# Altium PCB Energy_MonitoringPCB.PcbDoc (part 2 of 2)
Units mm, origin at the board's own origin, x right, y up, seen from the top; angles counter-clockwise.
Board outline 101.22 x 43.37 mm, 4 copper layers (Top Layer, Int1 (GND), Int2 (PWR), Bottom Layer), stack 1.527 mm thick; 86 components, 79 nets, 384 pads, 136 vias.
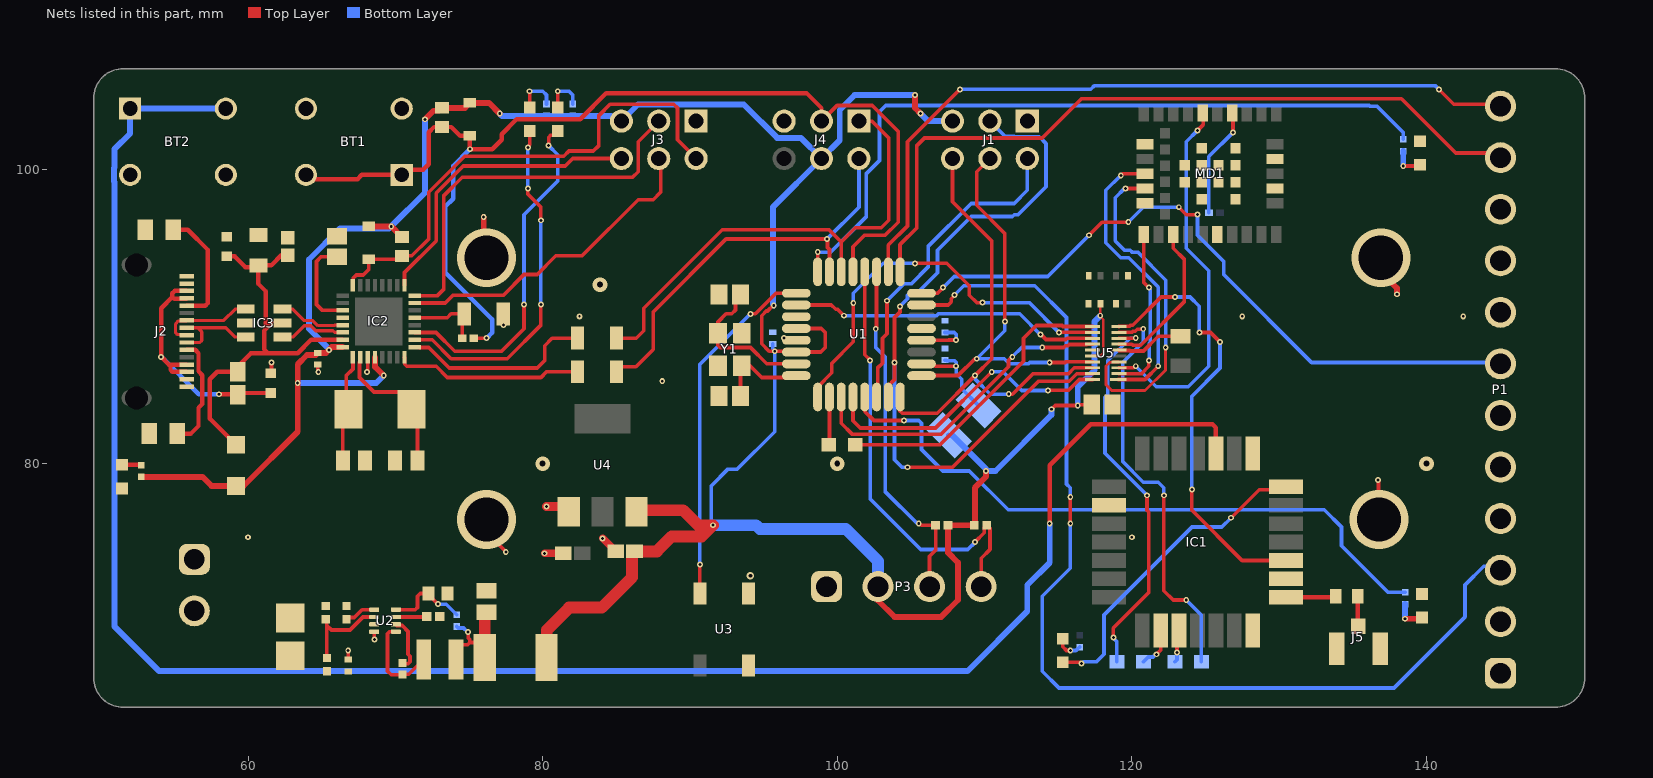
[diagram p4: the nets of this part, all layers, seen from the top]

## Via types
v1: diameter 0.4, hole 0.2, Top Layer to Bottom Layer, 120 vias
v2: diameter 0.4, hole 0.16, Top Layer to Bottom Layer, 6 vias
v3: diameter 1, hole 0.4, Top Layer to Bottom Layer, 4 vias
v4: diameter 4, hole 3, Top Layer to Bottom Layer, 4 vias
v5: diameter 0.4, hole 0.2, Top Layer to Int2 (PWR), 1 vias
v6: diameter 0.508, hole 0.254, Top Layer to Int1 (GND), 1 vias

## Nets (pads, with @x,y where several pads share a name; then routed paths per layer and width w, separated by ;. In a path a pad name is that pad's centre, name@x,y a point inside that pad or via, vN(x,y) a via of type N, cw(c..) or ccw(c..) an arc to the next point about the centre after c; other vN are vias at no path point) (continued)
+5V_OUT: C6.2 C15.2 C24.2 C25.2 C26.2 D1.1 D4.1 D5.1 F1.2 IC2.4 IC2.32 J1.5 J3.5 J4.4 L2.2 P3.2 R7.1 R10.1 R13.1 R14.1 R16.1 R17.1 R25.1 U1.4 U1.6 U4.3 U5.16 | length 210.8
  Top Layer w0.17: U5.16@117.326,87.31 117.341,87.325 117.873,87.325 118.061,87.512 118.061,89.776 117.856,89.981 117.856,90.856 C24.2@117.864,90.864
  Top Layer w0.25: v1(95.691,90.745) 95.651,90.745 95.269,90.362 95.188,90.362 94.869,90.043 94.869,88.138 95.377,87.63 v1(95.758,87.63) 96.774,87.63 96.831,87.573 U1.6@97.223,87.573 98.876,87.573 99.187,87.884 99.187,88.9 98.914,89.173 U1.4@97.223,89.173 ; v1(114.554,83.693) 114.808,83.947 v1(116.332,83.947) 116.39,84.005 C25.2@117.283,84.005
  Top Layer w0.4: R7.1@52.739,79.102 56.915,79.102 57.531,78.486 59.179,78.486 D5.1@59.182,78.483 59.687,78.483 63.373,82.169 v1(63.373,85.471) 63.373,86.741 64.008,87.376 64.596,87.376 C26.2@64.742,87.522 65.297,87.522 v1(65.49,87.715) 65.683,87.908 IC2.32@66.421,87.908 ; D4.1@68.199,96.111 v1(69.724,96.111) R25.1@70.443,95.392 ; IC2.4@68.621,87.208 68.621,86.573 v1(69.215,85.979) ; v1(72.009,103.378) 72.586,103.955 72.952,103.955 R10.1@73.152,104.155 74.719,104.155 D1.1@75.057,104.493 76.355,104.493 v1(77.089,103.759) ; P3.2@102.771,71.653 102.771,70.711 103.886,69.596 107.061,69.596 108.204,70.739 108.204,73.279 107.53,73.953 R16.1@107.53,75.819 R17.1@109.303,75.819 109.347,75.819 109.347,78.359 110.109,79.121 v1(110.109,79.502) ; v1(105.283,105.029) 105.283,104.14 v1(105.664,103.759)
  Top Layer w0.8: F1.2@80.273,66.836 80.273,68.698 81.8,70.225 84.01,70.225 86.073,72.288 86.073,73.875 C6.2@86.239,74.041 87.757,74.041 88.773,75.057 90.805,75.057 v1(91.567,75.819) 90.551,75.819 89.535,76.835 86.476,76.835 U4.3@86.374,76.733
  Bottom Layer w0.25: v1(91.567,75.819) 91.44,75.946 91.44,78.486 92.583,79.629 93.218,79.629 95.758,82.169 v1(95.758,87.63) 95.631,87.757 C15.2@95.631,88.119
  Bottom Layer w0.4: v1(63.373,85.471) 68.707,85.471 v1(69.215,85.979) ; v1(65.49,87.715) 65.49,87.799 64.135,89.154 64.135,93.853 66.252,95.97 69.583,95.97 v1(69.724,96.111) 72.009,98.396 v1(72.009,103.378) ; v1(77.089,103.759) 77.235,103.613 R13.1@80.264,103.613 R14.1@82.042,103.613 84.665,103.613 85.027,103.251 J3.5@85.344,103.251 86.479,104.386 93.653,104.386 95.923,102.116 97.528,102.116 J4.4@98.933,100.711 ; v1(95.691,90.745) 95.631,90.805 95.631,97.409 J4.4@98.933,100.711 ; v1(105.283,105.029) 101.186,105.029 100.171,104.014 100.171,101.949 J4.4@98.933,100.711 ; v1(105.664,103.759) 106.172,103.251 J1.5@107.826,103.251 ; L2.2@107.577,81.93 107.808,81.93 110.109,79.629 v1(110.109,79.502) 110.744,79.502 114.554,83.312 v1(114.554,83.693) ; v1(116.332,83.947) 116.332,85.217 117.475,86.36 117.475,89.662 v1(117.856,90.043)
  Bottom Layer w0.8: v1(91.567,75.819) 94.488,75.819 94.742,75.565 100.584,75.565 102.771,73.378 P3.2@102.771,71.653
+12V_IN: C2.1 C3.2 P1.1 P1.5 P1.9 P2.2 R1.2 U2.3
CC1: J2.A5 R8.2 | length 8
  Top Layer w0.3: R8.2@54.925,95.885 55.9,95.885 57.277,94.508 57.277,90.901 57.101,90.725 J2.A5@55.839,90.725
CC2: J2.B5 R9.2 | length 7.7
  Top Layer w0.3: R9.2@55.179,82.042 56.124,82.042 56.639,82.556 56.639,83.792 56.896,84.049 56.896,86.006 56.639,86.264 56.639,86.572 56.639,87.499 56.413,87.725 J2.B5@55.839,87.725
DTR_RESET: BT1.1 BT1.2 C20.2 D1.2 J4.3 R10.2 U1.29 | length 76
  Top Layer w0.25: C20.2@75.32,88.516 75.323,88.519 v1(76.2,88.519) ; J4.3@98.933,103.251 99.993,104.311 102.372,104.311 104.14,102.543 104.14,96.393 103.251,95.504 101.854,95.504 101.073,94.723 U1.29@101.073,93.023
  Top Layer w0.3: BT1.2@63.933,99.604 64.223,99.314 67.437,99.314 67.727,99.604 BT1.1@70.433,99.604 70.778,99.949 71.882,99.949 72.263,100.33 72.263,102.489 72.629,102.855 R10.2@73.152,102.855 73.802,102.855 74.394,102.263 D1.2@75.057,102.263 v1(75.057,101.346) 76.581,101.346 77.216,101.981 77.216,102.362 78.232,103.378 82.55,103.378 84.328,105.156 97.917,105.156 98.933,104.14 J4.3@98.933,103.251
  Bottom Layer w0.3: v1(75.057,101.346) 73.925,100.214 73.925,97.986 73.406,97.467 73.406,92.964 76.581,89.789 76.581,88.9 v1(76.2,88.519)
GND: BT1.3 BT1.4 BT2.3 BT2.4 C2.2 C3.1 C4.1 C5.2 C6.1 C7.1 C8.2 C9.2 C10.2 C11.2 C12.1 C13.1 C14.1 C15.1 C16.1 C17.2 C18.2 C19.2 C21.1 C22.1 C23.1 C24.1 C25.1 C26.1 IC1.2 IC1.14 IC1.16 IC1.22 IC2.3 IC2.28 IC3.2 J1.1 J2.A1 J2.A12 J2.B1 J2.B12 J3.1 J4.5 J5.2 J5.3 LED1.1 LED2.1 LED3.1 MD1.6 MD1.12 MD1.14 MD1.26 MD1.30 MD1.37 MD1.38 MD1.39 MD1.40 MD1.41 MD1.42 MD1.43 MD1.44 MD1.45 MD1.46 MD1.47 MD1.48 P1.2 P1.4 P1.6 P1.8 P1.10 P2.1 P3.1 R3.1 R4.1 R5.1 R8.1 R9.1 R15.2 U1.3 U1.5 U1.21 U2.4 U3.2 U3.3 U4.1 U5.15 Y1.2 Y1.4 | length 18.8
  Top Layer w0.25: C8.2@61.542,86.146 61.595,86.199 v1(61.595,86.868) ; C26.1@64.742,86.722 64.742,86.261 v1(64.77,86.233) ; C3.1@66.802,66.694 v1(66.802,67.31) ; v1(68.072,86.233) 68.121,86.282 IC2.3@68.121,87.208 ; U2.4@68.564,68.588 68.564,68.088 v1(68.58,68.072) ; U4.1@81.418,77.089 U4.1@81.774,76.733 ; v1@84.074,74.924 v1(84.074,74.93)
  Top Layer w0.254: v4(76.2,76.2) 76.2,75.34 77.5,74.04 v1(77.5,74) ; v1(136.725,78.9) 136.752,78.873 136.752,76.227 v4(136.779,76.2)
  Top Layer w0.4: v1(76,96.75) 76,94.18 v4(76.2,93.98) ; v4(136.906,93.98) 136.906,93.006 138,91.912 v1(138,91.5)
  Top Layer w0.5: v1(80.137,73.914) C7.1@81.401,73.914 ; v1@84.074,74.924 C6.1@84.957,74.041
  Top Layer w0.6: v1(80.264,77.089) U4.1@81.418,77.089
  other v1: 96.393,88.519 77.343,89.408
  other v2: 60,75 120,75 88.125,85.6 82.5,90 127.5,90 142.5,90
  other v3: 80,80 100,80 140,80 83.9,92.15
  other v6: 94.107,72.39
ICSP_CLK: J1.4 U1.17 U5.17 | length 27.8
  Top Layer w0.25: U1.17@105.723,85.973 106.42,85.973 106.426,85.979 108.204,85.979 109.347,87.122 v1(109.474,87.122) ; J1.4@110.366,100.711 109.474,99.819 109.474,97.536 111.379,95.631 v1(111.379,89.662) ; v1(114.427,86.868) 115.484,86.868 115.525,86.91 U5.17@117.326,86.91
  Bottom Layer w0.25: v1(111.379,89.662) 111.379,89.027 v1(109.474,87.122) 111.342,87.122 111.69,86.774 112.991,86.774 113.085,86.868 v1(114.427,86.868)
ICSP_MISO: J1.6 U1.16 U5.18 | length 33.2
  Top Layer w0.25: U1.16@104.273,84.523 104.273,84.703 104.267,84.709 104.267,83.566 104.41,83.423 106.791,83.423 v1(109.347,85.979) 110.49,87.122 110.49,95.123 107.826,97.787 J1.6@107.826,100.711 ; v1(111.646,84.714) 111.892,84.714 113.284,86.106 115.697,86.106 116.101,86.51 U5.18@117.326,86.51
  Bottom Layer w0.25: v1(109.347,85.979) 109.347,85.752 110.385,84.714 v1(111.646,84.714)
ICSP_MOSI: J1.3 U1.15 U5.19 | length 51
  Top Layer w0.25: U1.15@103.473,84.523 103.473,85.293 103.886,85.706 v1(103.886,86.868) 103.886,89.916 104.267,90.297 v1(104.267,90.678) ; v1(104.775,79.756) 107.823,79.756 113.665,85.598 115.755,85.598 116.266,86.11 U5.19@117.326,86.11
  Bottom Layer w0.25: v1(103.886,86.868) 103.886,80.264 104.394,79.756 v1(104.775,79.756) ; v1(104.267,90.678) 104.775,91.186 104.775,91.44 104.902,91.567 105.41,91.567 106.807,92.964 106.807,94.488 109.093,96.774 111.887,96.774 112.014,96.901 112.268,96.901 114.173,98.806 114.173,101.727 113.709,102.191 112.007,102.191 111.963,102.235 111.382,102.235 J1.3@110.366,103.251
ICSP_SS: J1.2 U1.14 | length 22.4
  Top Layer w0.25: U1.14@102.673,84.523 102.673,85.147 102.743,85.217 102.743,86.487 103.073,86.817 103.073,88.511 103.378,88.816 v1(103.378,91.059)
  Bottom Layer w0.25: v1(103.378,91.059) 104.535,92.216 105.043,92.216 106.172,93.345 106.172,94.742 109.093,97.663 112.014,97.663 112.906,98.555 J1.2@112.906,100.711
L_LIVE: D3.1 IC1.21 | length 21.7
  Top Layer w0.25: D3.1@115.316,66.51 116.497,66.51 v1(116.586,66.421) ; v1(126.746,76.327) 128.651,78.232 130.266,78.232 IC1.21@130.46,78.426
  Bottom Layer w0.25: v1(116.586,66.421) 116.713,66.548 117.602,66.548 118.11,67.056 118.11,69.723 124.079,75.692 126.111,75.692 v1(126.746,76.327)
LL_NRST: IC1.17 U5.10 | length 30
  Top Layer w0.25: U5.10@119.126,89.31 119.151,89.335 119.847,89.335 119.907,89.394 120.07,89.394 121.989,91.313 v1(122.936,91.313) ; v1(124.079,78.232) 124.079,76.835 127.488,73.426 IC1.17@130.46,73.426 ; v1(124.587,88.9) 125.349,88.9 v1(125.984,88.265)
  Bottom Layer w0.25: v1(122.936,91.313) 123.952,91.313 124.587,90.678 v1(124.587,88.9) ; v1(124.079,78.232) 124.079,84.582 125.984,86.487 v1(125.984,88.265)
LLRX: R21.1 U5.9 | length 28.3
  Top Layer w0.25: U5.9@119.126,88.91 119.988,88.91 120.072,88.994 120.236,88.994 120.367,89.125 120.748,89.125 v1(120.777,89.154) ; v1(122.174,77.851) 122.174,71.374 122.809,70.739 v1(123.698,70.739)
  Bottom Layer w0.25: v1(120.777,89.154) 120.777,88.265 119.38,86.868 119.38,80.137 120.777,78.74 121.793,78.74 122.174,78.359 v1(122.174,77.851) ; v1(123.698,70.739) 124.725,69.712 R21.1@124.725,66.548
LLTX: R20.1 U5.8 | length 26.5
  Top Layer w0.25: v1(118.745,68.199) 118.745,68.834 121.158,71.247 121.158,76.708 121.031,76.835 v1(121.031,77.851) ; U5.8@119.126,88.51 120.26,88.51 v1(120.269,88.519)
  Bottom Layer w0.25: v1(118.745,68.199) 118.745,68.158 118.988,67.915 R20.1@118.988,66.548 ; v1(120.269,88.519) 119.888,88.519 118.364,86.995 118.364,84.686 118.176,84.498 118.176,80.706 v1(121.031,77.851)
LNRST: R22.1 U1.10 | length 3.2
  Top Layer w0.25: R22.1@99.473,81.28 U1.10@99.473,84.523
LoRa_live: D3.2 R24.1 | length 1.9
  Top Layer w0.25: D3.2@115.316,68.11 115.316,67.564 115.57,67.31 v1(115.824,67.31)
  Bottom Layer w0.25: v1(115.824,67.31) 116.205,67.31 116.459,67.564 R24.1@116.459,67.545
LoRa_RST: BT2.1 BT2.2 IC1.24 | length 131.9
  Top Layer w0.3: v1(114.427,75.946) 114.427,79.883 117.221,82.677 125.476,82.677 125.71,82.443 IC1.24@125.71,80.676
  Bottom Layer w0.4: BT2.2@58.495,104.104 BT2.1@51.995,104.104 51.995,102.414 50.927,101.346 50.927,100.092 50.895,100.06 50.895,99.148 50.927,99.116 50.927,68.961 53.975,65.913 108.839,65.913 112.903,69.977 112.903,71.755 114.427,73.279 v1(114.427,75.946)
LORARX: IC1.10 R21.2 | length 2.2
  Top Layer w0.25: v1(123.063,67.183) 123.063,68.159 123.21,68.306 IC1.10@123.21,68.676
  Bottom Layer w0.25: R21.2@122.925,66.548 123.063,66.686 v1(123.063,67.183)
LORATX: IC1.9 R20.2 | length 2.8
  Top Layer w0.25: v1(121.666,67.056) 121.96,67.35 IC1.9@121.96,68.676
  Bottom Layer w0.25: R20.2@120.788,66.548 121.113,66.873 121.442,66.873 121.625,67.056 v1(121.666,67.056)
MCU_AVCC: C14.2 L2.1 U1.18 | length 6.8
  Top Layer w0.25: U1.18@105.723,86.773 106.493,86.773 106.652,86.614 v1(108.077,86.614)
  Bottom Layer w0.25: C14.2@107.315,87.027 107.41,87.027 107.442,86.995 107.95,86.995 108.077,86.868 v1(108.077,86.614) 108.077,86.106 108.458,85.725 108.458,85.082 L2.1@109.593,83.947
MNRST: R22.2 U5.11 | length 20.5
  Top Layer w0.25: R22.2@101.144,81.28 106.98,81.28 112.649,86.949 112.649,88.519 113.505,89.375 115.259,89.375 115.324,89.31 U5.11@117.326,89.31
MRX: U1.9 U5.12 | length 27.4
  Top Layer w0.25: U1.9@98.673,84.523 98.673,85.211 99.625,86.163 99.625,86.8 101.092,88.267 v1(101.092,90.901) ; v1(105.283,93.599) 107.442,93.599 108.966,92.075 108.966,91.44 109.474,90.932 v1(109.855,90.932) ; v1(115.062,88.9) 115.072,88.91 U5.12@117.326,88.91
  Bottom Layer w0.25: v1(101.092,90.901) 101.092,91.567 103.124,93.599 v1(105.283,93.599) ; v1(109.855,90.932) 113.03,90.932 v1(115.062,88.9)
MTX: U1.2 U5.13 | length 21.2
  Top Layer w0.25: U1.2@97.223,90.773 99.6,90.773 99.899,90.474 100.026,90.474 v1(100.457,90.043) ; v1(113.792,88.773) 113.833,88.773 114.181,88.425 115.524,88.425 115.608,88.51 U5.13@117.326,88.51
  Bottom Layer w0.25: v1(100.457,90.043) 106.739,90.043 106.87,90.175 112.39,90.175 v1(113.792,88.773)
OSC1: C12.2 U1.7 Y1.1 | length 10.1
  Top Layer w0.25: C12.2@93.435,91.486 93.091,91.142 93.091,90.424 92.837,90.17 92.456,90.17 91.91,89.624 Y1.1@91.91,88.857 91.91,88.049 92.077,87.882 94.109,87.882 95.218,86.773 U1.7@97.223,86.773
OSC2: C13.2 U1.8 Y1.3 | length 6.2
  Top Layer w0.25: C13.2@93.435,84.582 93.435,86.582 Y1.3@93.51,86.657 94.064,86.657 94.869,85.852 97.102,85.852 U1.8@97.223,85.973
PROG_RX: J4.2 R12.1 U1.31 | length 28.2
  Top Layer w0.25: R12.1@85.018,86.233 85.018,86.261 85.343,86.586 86.332,86.586 87.503,87.757 87.503,90.297 92.456,95.25 v1(99.314,95.25) 99.34,95.224 99.34,94.675 99.473,94.542 U1.31@99.473,93.023
  Bottom Layer w0.25: v1(99.314,95.25) 101.473,97.409 J4.2@101.473,100.711
PROG_TX: J4.1 R11.1 U1.30 | length 33.5
  Top Layer w0.25: R11.1@85.018,88.519 86.36,88.519 86.868,89.027 86.868,90.551 92.202,95.885 99.441,95.885 100.273,95.053 ; U1.30@100.273,93.023 100.273,95.053 ; J4.1@101.473,103.251 102.362,103.251 103.505,102.108 103.505,96.52 102.997,96.012 101.232,96.012 100.273,95.053
PW_OUT: C5.1 F1.1 L1.2 R2.2 | length 7.9
  Top Layer w0.25: L1.2@74.125,66.7 74.125,67.33 74.5,67.705 74.911,67.705 75.057,67.852 ; v1(74.93,68.58) 74.959,68.551 74.959,68.157 75.057,68.059 75.057,67.852 ; F1.1@76.073,66.836 76.073,67.227 75.448,67.852 75.057,67.852 ; C5.1@76.073,69.793 C5.1@76.2,69.92
  Top Layer w0.8: F1.1@76.073,67.227 C5.1@76.073,69.793
  Bottom Layer w0.25: R2.2@74.168,68.942 74.268,68.842 74.627,68.842 74.889,68.58 v1(74.93,68.58)
PWR_AREF: C16.2 U1.20 | length 3.6
  Top Layer w0.25: U1.20@105.723,88.373 107.55,88.373 107.569,88.392 v1(108.077,88.392)
  Bottom Layer w0.25: C16.2@107.315,88.9 107.95,88.9 108.077,88.773 v1(108.077,88.392)
PWR_EN: R1.1 R3.2 U2.2 | length 6.4
  Top Layer w0.25: R3.2@65.278,69.434 65.348,69.364 65.348,69.018 ; R1.1@65.348,66.802 65.348,69.018 ; U2.2@68.564,69.588 67.81,69.588 66.929,68.707 65.659,68.707 65.348,69.018
PWR_FB: R2.1 R5.2 U2.8 | length 5.7
  Top Layer w0.25: U2.8@70.044,70.088 71.358,70.088 71.501,70.231 71.501,70.993 71.692,71.184 R5.2@72.248,71.184 72.248,71.109 72.882,70.475 v1(72.887,70.475)
  Bottom Layer w0.25: v1(72.887,70.475) 72.915,70.448 73.462,70.448 R2.1@74.168,69.742
PWR_LED: LED2.2 R7.2 | length 1.3
  Top Layer w0.3: LED2.2@51.435,79.921 52.72,79.921 R7.2@52.739,79.902
PWR_PST: C1.1 U2.6 | length 3.7
  Top Layer w0.25: U2.6@70.044,69.088 70.119,69.013 70.464,69.013 70.866,68.611 70.866,67.056 70.993,66.929 70.993,66.548 70.866,66.421 70.537,66.421 C1.1@70.485,66.473
PWR_RT: R4.2 U2.1 | length 2.1
  Top Layer w0.25: R4.2@66.675,69.434 66.8,69.559 67.215,69.559 67.744,70.088 U2.1@68.523,70.088
PWR_SS: C4.2 U2.7 | length 2.1
  Top Layer w0.25: U2.7@70.044,69.588 72.094,69.588 C4.2@72.136,69.63
PWR_SW: C1.2 L1.1 U2.5 | length 6.2
  Top Layer w0.25: U2.5@70.044,68.588 69.604,68.588 69.469,68.453 69.469,65.913 69.723,65.659 70.451,65.659 C1.2@70.485,65.693 70.917,65.693 L1.1@71.925,66.7
RF_IN: J5.1 R23.2 | length 2
  Top Layer w0.331: R23.2@135.339,70.993 135.339,69.005 J5.1@135.382,68.962
RF_OUT: IC1.15 R23.1 | length 3.4
  Top Layer w0.331: IC1.15@130.46,70.926 133.772,70.926 R23.1@133.839,70.993
RGB: U1.1 U3.4 | length 24.1
  Top Layer w0.25: v1(90.678,73.152) U3.4@90.679,71.191 U3.4@90.679,71.191 ; v1(94.107,90.17) 94.445,90.17 95.848,91.573 U1.1@97.223,91.573
  Bottom Layer w0.25: v1(90.678,73.152) 90.678,86.741 v1(94.107,90.17)
SCL: P3.4 R17.2 U1.28 | length 30.4
  Top Layer w0.25: U1.28@101.873,93.023 101.873,87.398 102.235,87.036 v1(102.235,86.995) ; v1(109.347,74.676) 109.978,75.307 109.978,75.669 110.128,75.819 110.178,75.819 110.378,75.619 110.378,74.177 109.771,73.57 P3.4@109.771,71.653
  Bottom Layer w0.25: v1(102.235,86.995) 102.235,77.597 105.664,74.168 108.865,74.168 109.347,74.65 v1(109.347,74.676)
SCLK: IC2.15 J3.4 | length 22.1
  Top Layer w0.25: IC2.15@71.321,90.908 73.382,90.908 73.914,91.44 77.343,91.44 78.74,92.837 79.629,92.837 80.899,94.107 82.677,94.107 86.487,97.917 87.503,97.917 88.011,98.425 88.011,100.584 J3.4@87.884,100.711
SDA: P3.3 R16.2 U1.27 | length 23.9
  Top Layer w0.25: v1(102.616,89.154) 102.616,89.195 102.673,89.252 U1.27@102.673,93.023 ; v1(105.537,75.946) 105.578,75.946 105.705,75.819 R16.2@106.68,75.819 106.68,74.116 106.271,73.707 P3.3@106.271,71.653
  Bottom Layer w0.25: v1(102.616,89.154) 102.616,87.884 103.251,87.249 103.251,78.105 105.41,75.946 v1(105.537,75.946)
SENS1: P1.3 U1.23 | length 72.6
  Top Layer w0.25: U1.23@105.723,90.773 107.537,90.773 107.745,90.981 107.745,91.194 107.95,91.399 v1(107.95,91.44) ; v1(115.824,75.946) v1(115.824,77.724)
  Bottom Layer w0.25: v1(107.95,91.44) 108.585,92.075 113.411,92.075 115.57,89.916 115.57,78.613 115.824,78.359 v1(115.824,77.724) ; v1(115.824,75.946) 115.824,72.898 113.919,70.993 113.919,65.913 115.062,64.77 137.795,64.77 142.621,69.596 142.621,71.755 143.902,73.036 P1.3@145.034,73.036
SENS2: P1.7 U1.24 | length 47.8
  Top Layer w0.25: U1.24@105.723,91.573 106.039,91.573 106.045,91.567 106.807,91.567 v1(107.188,91.948) ; v1(117.094,95.504) 117.983,96.393 v1(119.761,96.393) ; v1(123.19,97.409) 123.698,96.901 v1(124.46,96.901)
  Bottom Layer w0.25: v1(107.188,91.948) 107.95,92.71 114.3,92.71 v1(117.094,95.504) ; v1(119.761,96.393) 120.777,97.409 v1(123.19,97.409) ; v1(124.46,96.901) 124.46,95.504 126.238,93.726 126.238,92.837 132.207,86.868 145.161,86.868 145.034,86.995 P1.7@145.034,87.036
SENS3: P1.11 U1.25 | length 51.5
  Top Layer w0.25: U1.25@104.273,93.023 104.273,93.212 104.267,93.218 104.267,94.869 105.41,96.012 105.41,101.6 105.918,102.108 113.919,102.108 116.586,104.775 138.303,104.775 141.986,101.092 144.978,101.092 P1.11@145.034,101.036
SENSOR_LED: R26.1 U1.32 | length 50.1
  Top Layer w0.25: U1.32@98.673,93.023 98.673,94.228 98.679,94.234 v1(98.679,94.361)
  Bottom Layer w0.25: v1(98.679,94.361) 99.568,94.361 101.981,96.774 101.981,99.695 102.87,100.584 102.87,103.886 103.295,104.311 136.1,104.311 136.144,104.267 136.652,104.267 138.43,102.489 R26.1@138.43,102.019
SENSOR_LED1: LED3.2 R26.2 | length 2.2
  Top Layer w0.25: v1(138.43,100.203) 139.484,100.203 LED3.2@139.573,100.292
  Bottom Layer w0.4: v1(138.43,100.203) R26.2@138.43,101.219
SMISO: IC2.17 J3.6 | length 20.7
  Top Layer w0.25: IC2.17@70.621,92.108 70.618,92.111 70.618,92.97 72.771,95.123 72.771,98.367 74.607,100.203 81.534,100.203 82.042,100.711 J3.6@85.344,100.711
SMOSI: IC2.16 J3.3 | length 26.4
  Top Layer w0.25: IC2.16@71.321,91.408 72.866,91.408 73.279,91.821 73.279,98.171 74.549,99.441 86.106,99.441 86.487,99.822 86.487,101.854 J3.3@87.884,103.251
SOSC1: C18.1 IC2.1 Y2.1 | length 7.4
  Top Layer w0.25: C18.1@66.433,80.214 66.433,83.315 Y2.1@66.811,83.693 66.675,83.829 66.675,85.979 67.121,86.425 IC2.1@67.121,87.208
SOSC2: C19.1 IC2.2 Y2.2 | length 9.7
  Top Layer w0.25: IC2.2@67.621,87.208 67.621,86.925 67.564,86.868 67.564,85.852 68.548,84.868 70.286,84.868 71.111,84.043 Y2.2@71.111,83.693 71.501,83.303 71.501,80.391 71.489,80.379 C19.1@71.489,80.214
SRESET: D4.2 IC2.24 J3.2 R25.2 | length 34.9
  Top Layer w0.25: IC2.24@67.126,92.113 67.146,92.133 67.146,92.597 67.357,92.808 67.821,92.808 68.199,93.186 D4.2@68.199,93.881 70.232,93.881 R25.2@70.443,94.092 70.458,94.107 71.12,94.107 72.263,95.25 72.263,98.425 74.709,100.871 81.44,100.871 81.788,101.219 83.439,101.219 83.82,101.6 83.82,103.632 84.582,104.394 88.9,104.394 89.154,104.14 89.154,101.981 J3.2@90.424,100.711
SRX: IC2.8 R12.2 | length 12.7
  Top Layer w0.25: IC2.8@70.621,87.208 70.646,87.183 70.646,86.75 70.792,86.604 72.781,86.604 73.533,85.852 79.883,85.852 80.264,86.233 R12.2@82.368,86.233
SRX_LED: D2.1 IC2.10 | length 23.6
  Top Layer w0.25: IC2.10@71.321,88.408 72.501,88.408 73.787,87.122 77.597,87.122 79.883,89.408 v1(79.883,90.805) ; v1(78.994,98.679) 78.994,98.298 79.883,97.409 v1(79.883,96.52) ; v1(78.994,101.473) 78.994,101.514 79.121,101.641 D2.1@79.121,102.578
  Bottom Layer w0.25: v1(78.994,98.679) v1(78.994,101.473) ; v1(79.883,90.805) v1(79.883,96.52)
STX: IC2.9 R11.2 | length 13.1
  Top Layer w0.25: IC2.9@71.321,87.908 71.604,87.908 71.628,87.884 72.263,87.884 73.66,86.487 79.629,86.487 80.137,86.995 80.137,88.011 80.645,88.519 R11.2@82.368,88.519
STX_LED: IC2.11 LED4.1 | length 23.6
  Top Layer w0.25: IC2.11@71.321,88.908 72.763,88.908 74.041,87.63 77.216,87.63 78.74,89.154 v1(78.74,90.805) ; v1(80.391,101.6) 80.42,101.629 80.42,102.157 80.566,102.303 80.751,102.303 LED4.1@81.026,102.578
  Bottom Layer w0.25: v1(78.74,90.805) 78.74,96.901 81.026,99.187 81.026,100.965 v1(80.391,101.6)
TEST: R6.1 U1.13 | length 44.5
  Top Layer w0.25: U1.13@101.873,84.523 101.873,83.547 102.489,82.931 v1(104.521,82.931)
  Bottom Layer w0.25: v1(104.521,82.931) 105.537,82.931 105.725,82.743 105.725,80.965 107.188,79.502 108.966,79.502 111.605,76.863 133.068,76.863 134.239,75.692 134.239,74.422 137.395,71.266 R6.1@138.557,71.266
TEST_LED: LED1.2 R6.2 | length 2.2
  Top Layer w0.4: v1(138.557,69.469) 139.7,69.469 LED1.2@139.7,69.558
  Bottom Layer w0.4: v1(138.557,69.469) R6.2@138.557,70.466 R6.2@138.557,70.485
TRANSLATOR_EN: R19.1 U5.6 | length 4.6
  Top Layer w0.25: U5.6@119.126,87.71 119.151,87.685 119.866,87.685 119.907,87.644 120.791,87.644 121.8,88.653 R19.1@123.306,88.653
UBRX: U1.11 U5.14 | length 21.9
  Top Layer w0.25: U1.11@100.273,84.523 100.273,82.734 101.002,82.005 107.055,82.005 111.633,86.583 111.633,86.995 v1(111.887,87.249) ; v1(113.919,87.884) 115.355,87.884 115.474,88.003 115.667,88.003 115.749,88.085 116.951,88.085 116.976,88.11 U5.14@117.326,88.11
  Bottom Layer w0.25: v1(111.887,87.249) 112.522,87.884 v1(113.919,87.884)
UBX_BLE_RX: MD1.3 U5.7 | length 10.6
  Top Layer w0.25: U5.7@119.126,88.11 120.007,88.11 120.072,88.044 120.614,88.044 123.571,91.001 123.571,93.853 122.809,94.615 MD1.3@122.809,95.556
UBX_CS: MD1.28 U5.1 | length 19.9
  Top Layer w0.25: U5.1@119.076,85.71 120.889,85.71 v1(121.793,86.614) ; v1(119.253,99.568) 119.294,99.568 119.406,99.681 MD1.28@120.884,99.681
  Bottom Layer w0.25: v1(119.253,99.568) 118.237,98.552 118.237,94.996 119.253,93.98 119.798,93.98 121.793,91.985 v1(121.793,86.614)
UBX_MISO: MD1.21 U5.3 | length 25.6
  Top Layer w0.25: U5.3@119.126,86.51 120.124,86.51 120.228,86.614 v1(120.269,86.614) ; v1(124.46,102.616) 124.841,102.997 124.841,103.774 MD1.21@124.809,103.806
  Bottom Layer w0.25: v1(120.269,86.614) 121.666,85.217 123.825,85.217 125.222,86.614 125.222,93.091 123.698,94.615 123.698,101.854 v1(124.46,102.616)
UBX_MOSI: MD1.1 U5.2 | length 11.4
  Top Layer w0.25: U5.2@119.126,86.11 120.654,86.11 121.158,86.614 v1(121.158,86.995) ; MD1.1@120.809,95.556 120.809,92.297 v1(121.158,91.948)
  Bottom Layer w0.25: v1(121.158,86.995) 121.177,87.014 121.177,88.165 121.252,88.24 121.252,91.813 121.158,91.907 v1(121.158,91.948)
UBX_SCLK: MD1.29 U5.4 | length 23
  Top Layer w0.2: U5.4@119.126,86.91 118.776,86.91 118.751,86.885 118.512,86.885 118.251,86.623 118.251,85.349 118.637,84.963 120.904,84.963 122.301,86.36 v1(122.301,87.884)
  Top Layer w0.25: v1(119.57,98.679) 120.904,98.679 120.902,98.681 MD1.29@120.884,98.681
  Bottom Layer w0.25: v1@119.634,98.679 v1(119.57,98.679) 119.507,98.679 118.872,98.044 118.872,95.123 119.507,94.488 119.888,94.488 120.015,94.361 120.396,94.361 122.301,92.456 v1(122.301,87.884)
UCS: U1.12 U5.20 | length 20.5
  Top Layer w0.25: U1.12@101.073,84.523 101.073,82.912 101.562,82.423 106.68,82.423 v1(110.49,86.233) ; v1(114.3,84.963) 114.329,84.992 115.714,84.992 116.432,85.71 U5.20@117.326,85.71
  Bottom Layer w0.25: v1(110.49,86.233) 111.252,86.233 112.522,84.963 v1(114.3,84.963)
USBIN: C9.1 C10.1 C11.1 D5.2 FB1.2 IC2.31 IC3.5 | length 28
  Top Layer w0.3: C9.1@58.557,94.067 59.095,94.067 59.817,93.345 60.588,93.345 C11.1@60.706,93.463 ; D5.2@59.182,81.283 59.179,81.283 57.404,83.058 57.404,85.725 57.912,86.233 FB1.2@59.309,86.233 59.309,86.36 59.182,86.487 60.198,87.503 61.341,87.503 ; IC3.5@62.337,89.54 61.6,89.54 61.214,89.154 ; C10.1@62.685,94.141 62.264,94.141 61.586,93.463 C11.1@60.706,93.463 ; IC2.31@66.421,88.408 64.278,88.408 63.373,87.503 61.341,87.503 ; C11.1@60.706,93.463 60.706,92.202 61.214,91.694 61.214,89.154 ; 61.214,89.154 61.087,89.027 61.087,87.757 61.341,87.503
USBIN_D_N: IC3.3 J2.A7 J2.B7 | length 6.5
  Top Layer w0.221: J2.A7@55.626,88.225 J2.A7@55.839,88.225 56.727,88.225 56.856,88.354 56.856,88.94 56.571,89.225 ; J2.B7@55.839,89.225 56.571,89.225 ; IC3.3@59.837,88.59 59.127,88.59 58.492,89.225 56.571,89.225
USBIN_D_P: IC3.1 J2.A6 J2.B6 | length 6.6
  Top Layer w0.221: J2.B6@55.839,88.725 55.799,88.765 55.208,88.765 55.078,88.894 55.078,89.488 55.276,89.685 55.799,89.685 J2.A6@55.839,89.725 58.361,89.725 59.127,90.49 IC3.1@59.837,90.49
USBLEDRX: D2.2 R13.2 | length 3
  Top Layer w0.25: D2.2@79.121,104.178 v1(79.121,105.283)
  Bottom Layer w0.25: v1(79.121,105.283) 80.01,105.283 80.264,105.029 R13.2@80.264,104.413
USBLEDTX: LED4.2 R14.2 | length 2.8
  Top Layer w0.25: LED4.2@81.026,104.178 v1(81.026,105.283)
  Bottom Layer w0.25: v1(81.026,105.283) 81.788,105.283 82.042,105.029 R14.2@82.042,104.413
USBMCU_D_N: IC2.30 IC3.4 | length 4.6
  Top Layer w0.221: IC3.4@62.337,88.59 63.047,88.59 63.823,89.366 64.262,89.366 64.601,89.027 65.767,89.027 65.886,88.908 IC2.30@66.421,88.908
USBMCU_D_P: IC2.29 IC3.6 | length 4.6
  Top Layer w0.221: IC3.6@62.337,90.49 63.047,90.49 63.823,89.714 64.406,89.714 64.745,89.375 65.852,89.375 65.886,89.408 IC2.29@66.421,89.408
USBS_DTR: C20.1 IC2.13 R15.1 | length 5.2
  Top Layer w0.25: IC2.13@71.321,89.908 73.525,89.908 73.787,90.17 R15.1@74.676,90.17 74.676,89.916 74.54,89.78 C20.1@74.54,88.516
USBS_UCAP: C17.1 IC2.27 | length 6.4
  Top Layer w0.25: C17.1@66.04,94.042 64.959,94.042 64.643,93.726 64.643,90.805 65.024,90.424 65.835,90.424 65.835,90.408 IC2.27@66.421,90.408
VBUS_OUT: C8.1 FB1.1 J2.A4 J2.A9 J2.B4 J2.B9 | length 18.8
  Top Layer w0.3: J2.A9@55.839,86.225 55.831,86.233 54.864,86.233 54.737,86.36 54.737,86.614 54.848,86.725 ; J2.B4@55.839,86.725 54.848,86.725 ; J2.B9@55.839,91.225 55.8,91.186 54.991,91.186 54.864,91.313 ; J2.A4@55.839,91.725 55.022,91.725 54.864,91.567 54.864,91.313 ; v1(58.039,84.709) 59.281,84.709 FB1.1@59.309,84.681 59.424,84.796 C8.1@61.542,84.796 ; 54.848,86.725 54.626,86.725 v1(54.102,87.249) 54.102,90.551 54.864,91.313
  Bottom Layer w0.3: v1(54.102,87.249) 54.122,87.249 56.662,84.709 v1(58.039,84.709)
VLG_S: P1.12 U1.26 | length 51.8
  Top Layer w0.25: U1.26@103.473,93.023 103.473,94.837 104.775,96.139 104.775,101.854 v1(108.331,105.41) ; v1(140.843,105.41) 141.859,104.394 144.892,104.394 P1.12@145.034,104.536
  Bottom Layer w0.25: v1(108.331,105.41) 117.221,105.41 117.475,105.664 140.589,105.664 v1(140.843,105.41)
W_RST: MD1.19 R18.2 | length 7.5
  Top Layer w0.25: MD1.19@126.809,103.806 126.873,103.742 v1(126.873,102.489)
  Bottom Layer w0.25: R18.2@125.228,97.028 125.228,100.844 v1(126.873,102.489)
pads on no net: IC1.3 IC1.4 IC1.5 IC1.6 IC1.7 IC1.8 IC1.11 IC1.12 IC1.13 IC1.18 IC1.19 IC1.20 IC1.23 IC1.25 IC1.26 IC1.27 IC1.28 IC2.5 IC2.6 IC2.7 IC2.12 IC2.14 IC2.18 IC2.19 IC2.20 IC2.21 IC2.22 IC2.23 IC2.25 IC2.26 IC2.33 J2.3 J2.4 J2.A8 J2.B8 MD1.2 MD1.4 MD1.5 MD1.7 MD1.8 MD1.11 MD1.13 MD1.15 MD1.16 MD1.17 MD1.18 MD1.20 MD1.22 MD1.23 MD1.24 MD1.25 MD1.27 MD1.31 MD1.32 MD1.33 MD1.34 MD1.35 MD1.36 U1.19 U1.22 U4.4

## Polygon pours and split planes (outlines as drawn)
GND on Top Layer "GND_L01_P016" (solid, pour order 16): 49.53,65.453 49.53,104.818 cw(c51.53,104.818) 51.53,106.818 148.749,106.818 cw(c148.749,104.818) 150.749,104.818 150.749,65.453 cw(c148.749,65.453) 148.749,63.453 51.53,63.453 cw(c51.53,65.453)
+12V_IN on Top Layer "+12V_IN_L01_P008" (solid, pour order 8): 67.564,65.278 68.58,64.262 86.614,64.262 87.122,64.77 87.122,64.897 86.868,65.151 86.487,65.151 86.106,64.77 69.088,64.77 68.072,65.786
+12V_IN on Top Layer "+12V_IN_L01_P009" (solid, pour order 9): 145.669,95.377 145.542,95.504 144.653,95.504 143.764,94.615 143.764,93.853 143.891,93.726 143.891,92.329 144.018,92.202 146.177,92.202 146.431,91.948 146.431,81.788 145.923,81.788 145.669,81.534 144.145,81.534 144.145,81.407 143.764,81.026 143.764,78.867 144.272,78.359 146.304,78.359 146.431,78.232 146.431,67.818 146.558,67.691 146.558,65.278 147.701,65.278 148.082,65.659 148.082,66.04 148.082,95.123 147.828,95.377
+12V_IN on Top Layer "+12V_IN_L01_P007" (solid, pour order 7): 86.868,64.643 86.868,64.516 146.939,64.516 147.701,65.278 147.701,67.31 147.193,67.818 143.637,67.818 143.637,67.437 141.351,65.151 88.646,65.151 88.265,65.151 87.63,65.151 86.868,65.151
+5V_OUT on Top Layer "+5V_OUT_L01_P005" (solid, pour order 5): 64.516,88.138 64.008,87.63 64.008,87.122 65.151,87.122 65.659,87.63 66.929,87.63 67.056,87.757 67.056,88.138
+12V_IN on Top Layer "+12V_IN_L01_P003" (solid, pour order 3): 68.707,69.342 68.834,69.215 68.961,69.215 68.961,68.961 68.834,68.834 68.199,68.834 68.072,68.707 68.072,65.786 67.564,65.278 64.77,65.278 63.627,65.278 58.928,65.278 54.864,69.342 54.864,71.501 55.118,71.755 58.547,71.755 58.547,70.358 60.96,67.945 64.008,67.945 64.516,67.437 64.516,66.294 64.643,66.167 67.31,66.167 67.818,66.675 67.818,69.088 68.072,69.342
GND on Bottom Layer "GND_L04_P017" (solid, pour order 17): 49.53,65.453 49.53,104.818 cw(c51.53,104.818) 51.53,106.818 148.749,106.818 cw(c148.749,104.818) 150.749,104.818 150.749,65.453 cw(c148.749,65.453) 148.749,63.453 51.53,63.453 cw(c51.53,65.453)
+3V3 on Int2 (PWR) (split plane): 148.916,106.301 149.081,106.273 149.242,106.226 149.396,106.162 149.543,106.082 149.679,105.985 149.804,105.873 149.915,105.748 150.012,105.612 150.093,105.466 150.157,105.311 150.203,105.15 150.231,104.985 150.24,104.833 150.239,104.818 150.239,65.453 150.24,65.438 150.231,65.286 150.203,65.121 150.157,64.96 150.093,64.806 150.012,64.659 149.915,64.523 149.804,64.398 149.679,64.287 149.543,64.19 149.396,64.109 149.242,64.045 149.081,63.999 148.916,63.971 148.764,63.962 148.749,63.963 51.53,63.963 51.515,63.962 51.363,63.971 51.198,63.999 51.037,64.045 50.883,64.109 50.736,64.19 50.6,64.287 50.475,64.398 50.364,64.523 50.267,64.659 50.186,64.806 50.122,64.96 50.076,65.121 50.048,65.286 50.039,65.438 50.04,65.453 50.04,104.818 50.039,104.833 50.048,104.985 50.076,105.15 50.122,105.311 50.186,105.466 50.267,105.612 50.364,105.748 50.475,105.873 50.6,105.985 50.736,106.082 50.883,106.162 51.037,106.226 51.198,106.273 51.363,106.301 51.515,106.309 51.53,106.308 148.749,106.308 148.764,106.309
GND on Int1 (GND) (split plane): 148.916,106.301 149.081,106.273 149.242,106.226 149.396,106.162 149.543,106.082 149.679,105.985 149.804,105.873 149.915,105.748 150.012,105.612 150.093,105.466 150.157,105.311 150.203,105.15 150.231,104.985 150.24,104.833 150.239,104.818 150.239,65.453 150.24,65.438 150.231,65.286 150.203,65.121 150.157,64.96 150.093,64.806 150.012,64.659 149.915,64.523 149.804,64.398 149.679,64.287 149.543,64.19 149.396,64.109 149.242,64.045 149.081,63.999 148.916,63.971 148.764,63.962 148.749,63.963 51.53,63.963 51.515,63.962 51.363,63.971 51.198,63.999 51.037,64.045 50.883,64.109 50.736,64.19 50.6,64.287 50.475,64.398 50.364,64.523 50.267,64.659 50.186,64.806 50.122,64.96 50.076,65.121 50.048,65.286 50.039,65.438 50.04,65.453 50.04,104.818 50.039,104.833 50.048,104.985 50.076,105.15 50.122,105.311 50.186,105.466 50.267,105.612 50.364,105.748 50.475,105.873 50.6,105.985 50.736,106.082 50.883,106.162 51.037,106.226 51.198,106.273 51.363,106.301 51.515,106.309 51.53,106.308 148.749,106.308 148.764,106.309

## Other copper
Top Layer:
  pour cut-out: 129.16,71.576 129.284,71.7 132.75,71.7 132.925,71.875 136.225,71.875 136.225,70.025 136.55,69.7 136.25,69.4 136.25,67.1 136.15,67 134.65,67 134.375,67.275 134.375,69.25 133.625,70 129.15,70 129.16,70.01

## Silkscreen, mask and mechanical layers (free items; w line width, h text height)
Top Overlay:
  text "URX" at 77.59,105.7 h1 r270
  text "UTX" at 81.99,105.6 h1 r270
  text "GND" at 111.94,105.328 h1.3
  text "MOSI" at 108.962,105.298 h1.3
  text "+5V" at 106.15,105.244 h1.3
  text "+5V" at 83.816,105.171 h1.3
  text "MOSI" at 86.737,105.171 h1.3
  text "GND" at 90.039,105.171 h1.3
  text "GND" at 95.246,105.171 h1.3
  text "DTR" at 98.294,105.152 h1.3
  text "TX" at 100.961,105.152 h1.3
  text "S4*" at 142.144,105.075 h1.3 r270
  text "WiFi+BLE" at 134.87,104.525 h1.52 r270
  text "M_ICSP" at 115.976,103.89 h1.52 r270
  text "U_ICSP" at 93.37,103.509 h1.52 r270
  text "UART" at 104.431,102.643 h1.52 r270
  text "S3" at 142.001,101.604 h1.3 r270
  text "GND" at 142.128,98.683 h1.3 r270
  text "MISO" at 106.549,97.932 h1.3
  text "CLK" at 109.851,97.932 h1.3
  text "SS" at 112.899,97.932 h1.3
  text "MOSI" at 83.816,97.805 h1.3
  text "CLK" at 87.245,97.805 h1.3
  text "RST" at 90.039,97.805 h1.3
  text "+3V3" at 94.992,97.805 h1.3
  text "+5V" at 98.167,97.805 h1.3
  text "RX" at 101.088,97.786 h1.3
  text "LORA" at 53.59,97.301 h1.52
  text "RESET" at 64.385,97.301 h1.52
  text "+12V" at 142.109,95.381 h1.3 r270
  text "GND" at 142.001,91.317 h1.3 r270
  text "S2" at 141.944,87.3 h1.3 r270
  text "GND" at 142.001,84.459 h1.3 r270
  text "+12V" at 141.982,81.157 h1.3 r270
  text "GND" at 141.874,77.601 h1.3 r270
  text "GND" at 53.336,76.727 h1.52
  text "LORA" at 132.353,74.934 h1.52 r270
  text "GND" at 98.04,73.929 h1.3
  text "+5V" at 101.723,73.929 h1.3
  text "SDA" at 105.279,73.929 h1.3
  text "SCL" at 108.835,73.929 h1.3
  text "RGB" at 91.182,73.806 h1.52
  text "S1" at 141.869,73.275 h1.3 r270
  text "GND" at 141.874,70.743 h1.3 r270
  text "+12V" at 141.855,67.187 h1.3 r270
  text "+12V" at 53.336,65.655 h1.52
Bottom Overlay:
  text "V1SA00" at 148.19,103.382 h1.52 r90
Mechanical 1:
  the board outline again, w0.254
